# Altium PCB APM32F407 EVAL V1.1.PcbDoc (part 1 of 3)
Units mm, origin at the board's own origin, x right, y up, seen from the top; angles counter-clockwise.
Board outline 133.48 x 125.98 mm, 2 copper layers (Top Layer, Bottom Layer); 143 components, 208 nets, 809 pads, 486 vias.
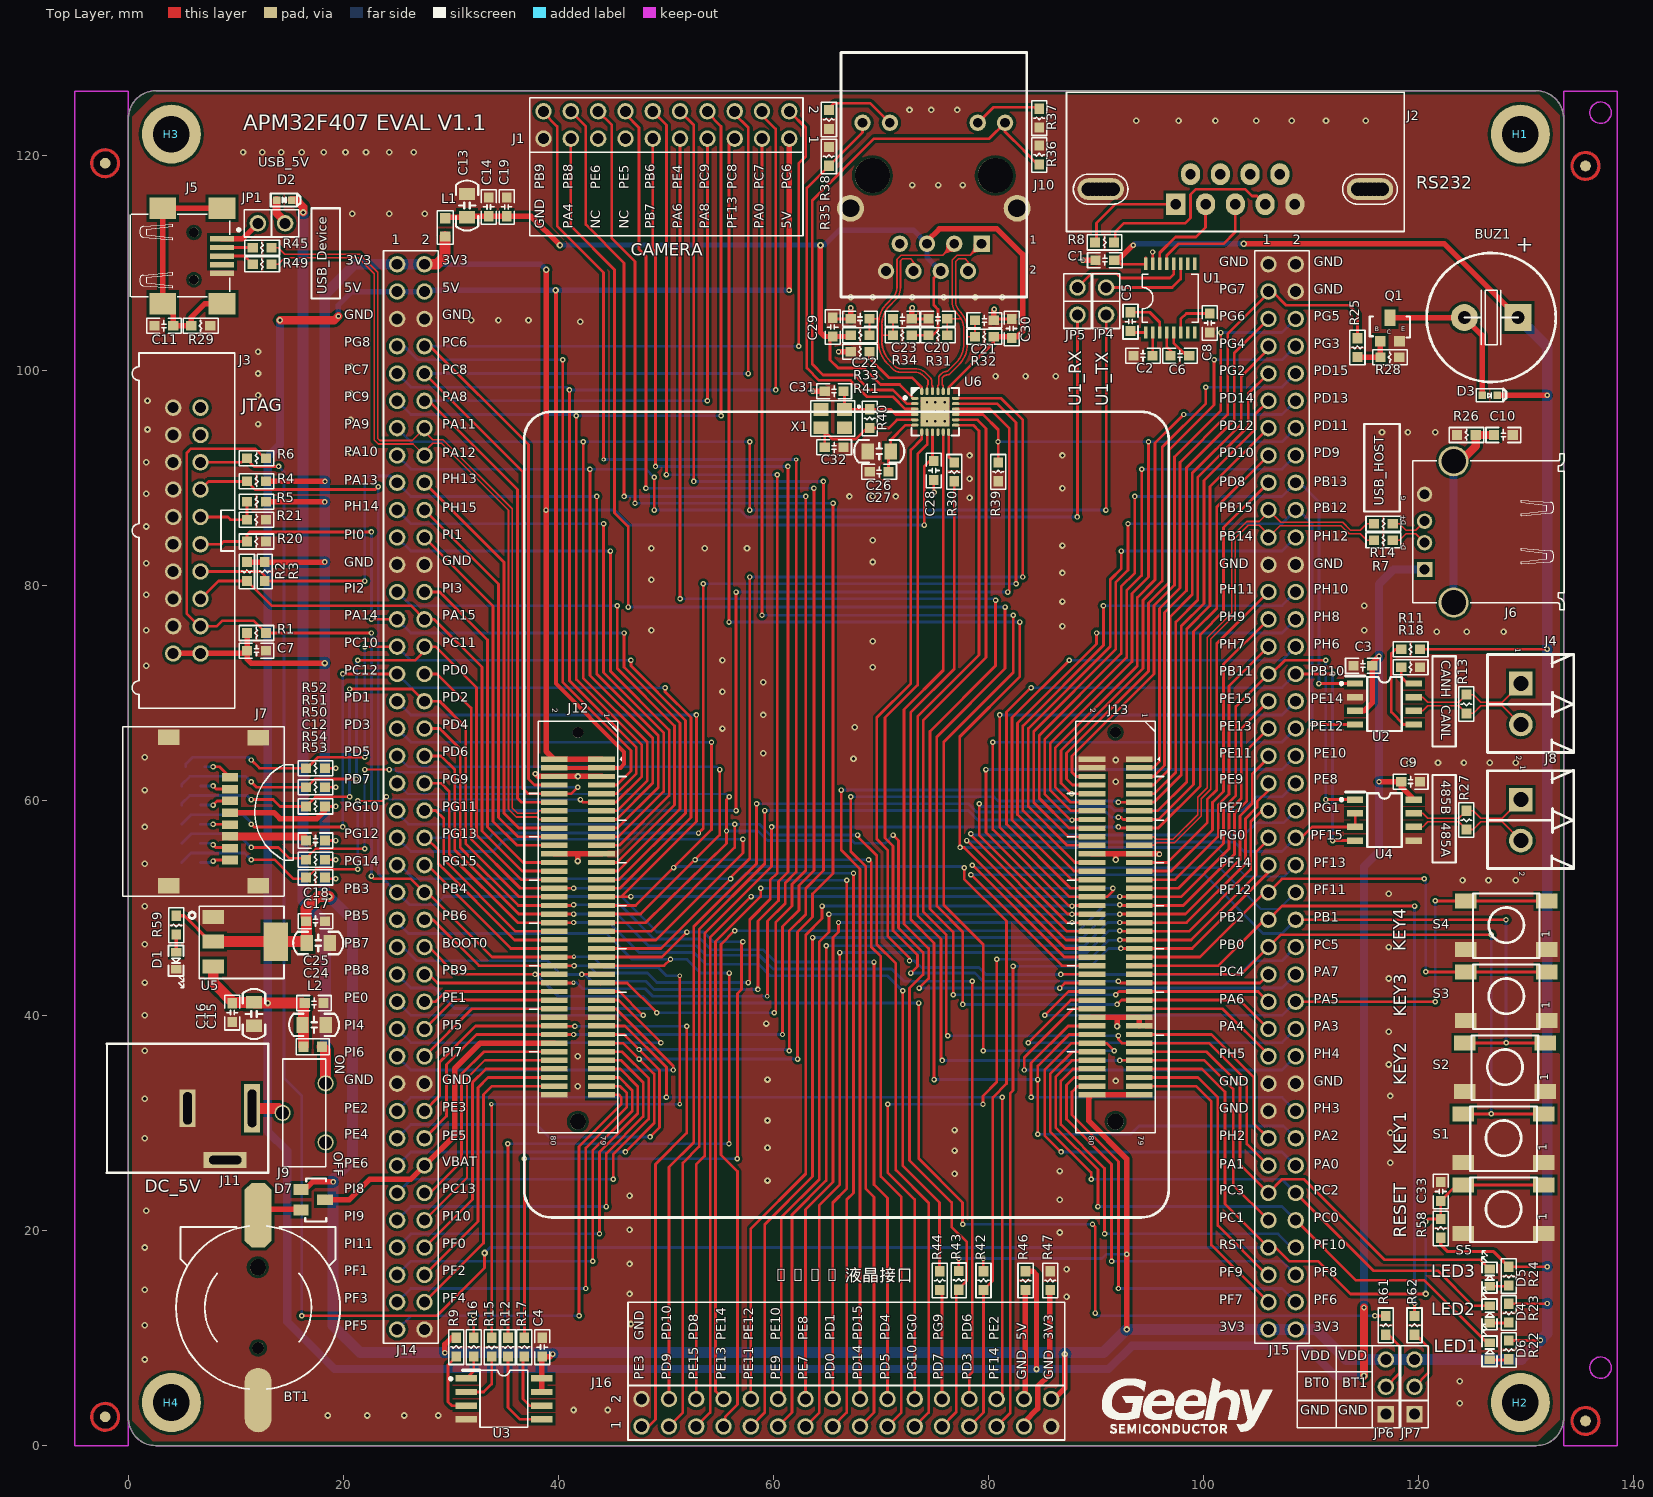
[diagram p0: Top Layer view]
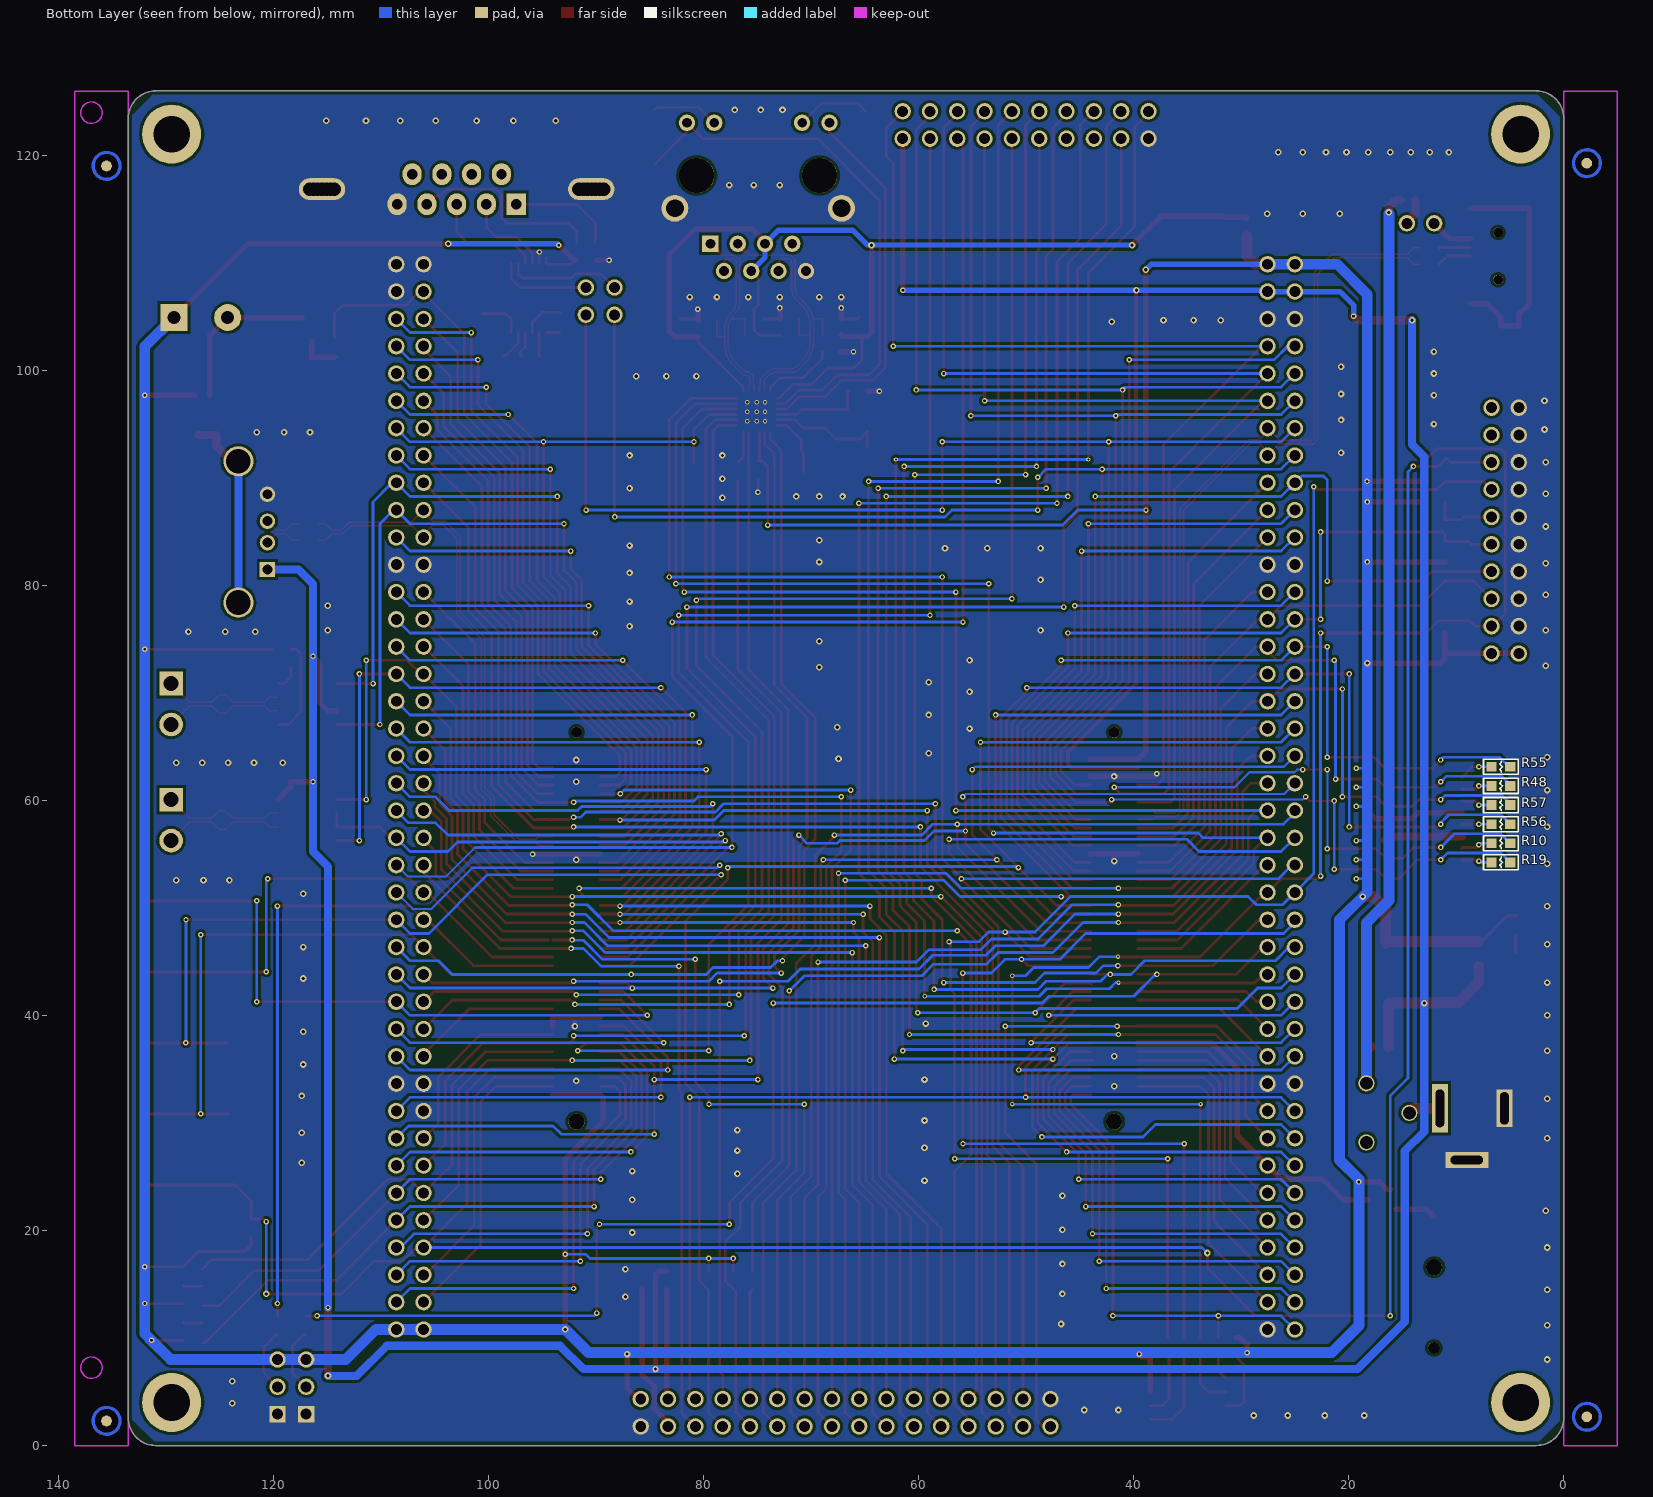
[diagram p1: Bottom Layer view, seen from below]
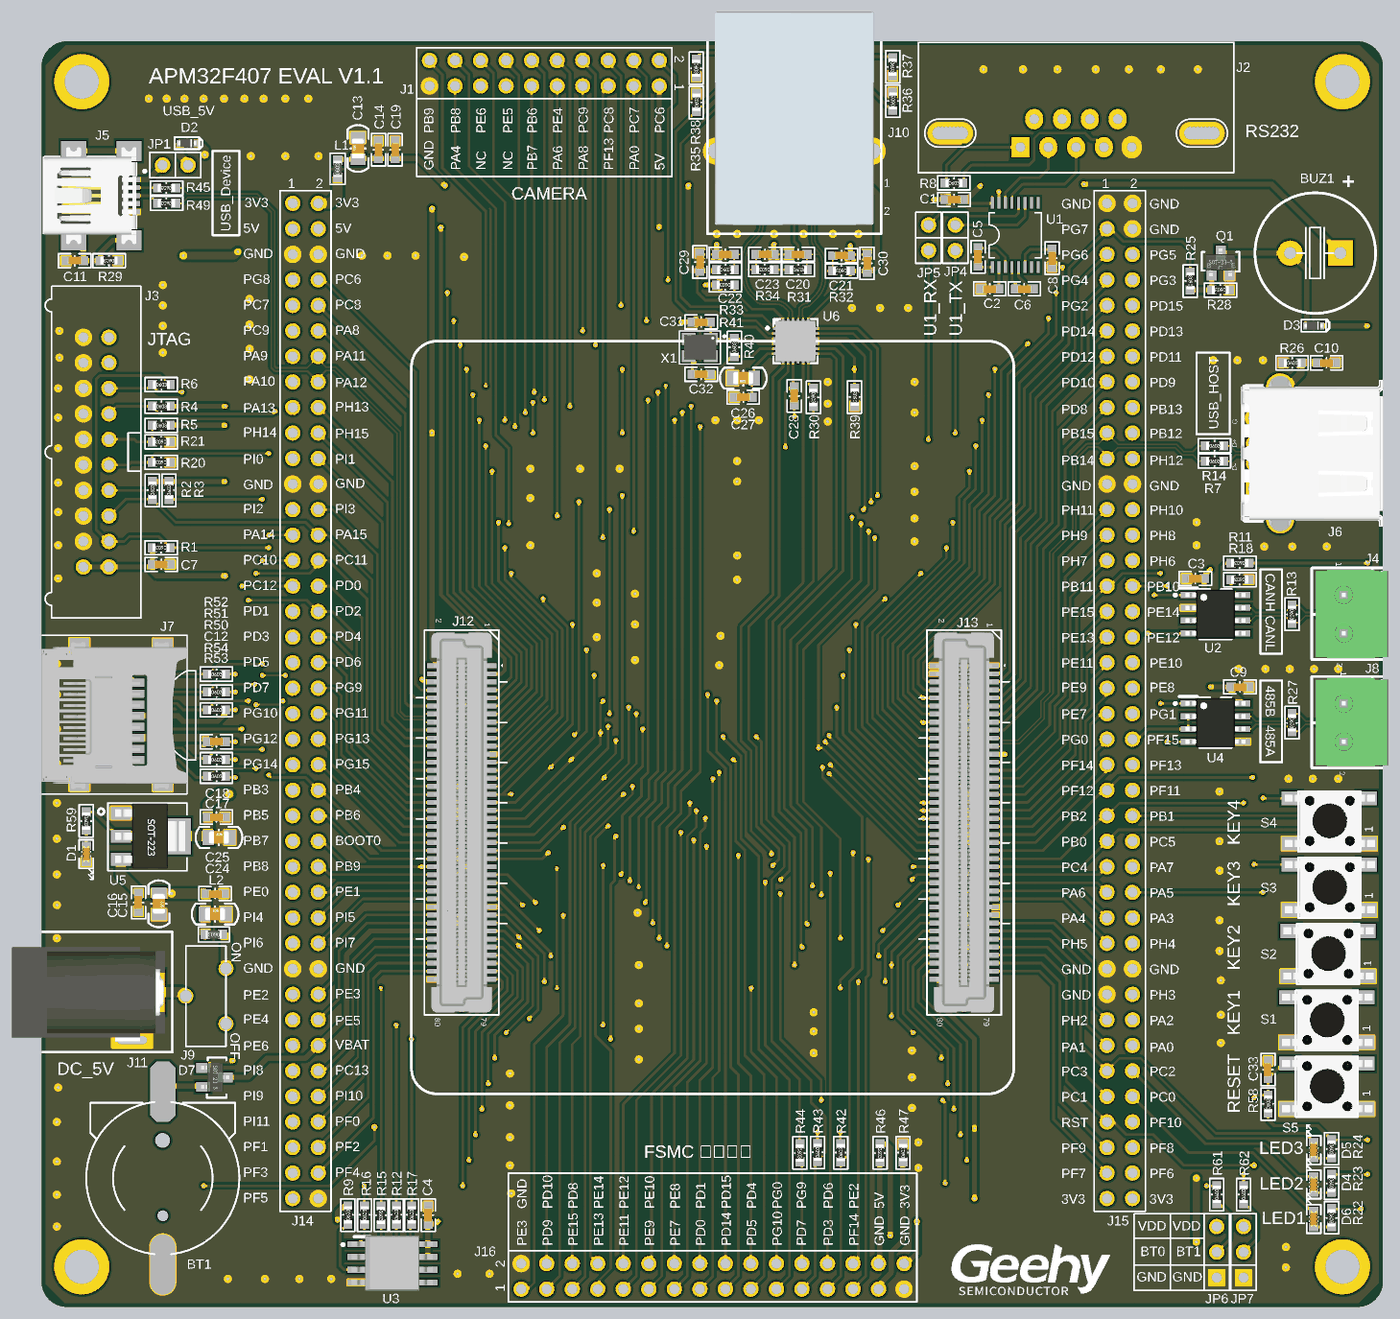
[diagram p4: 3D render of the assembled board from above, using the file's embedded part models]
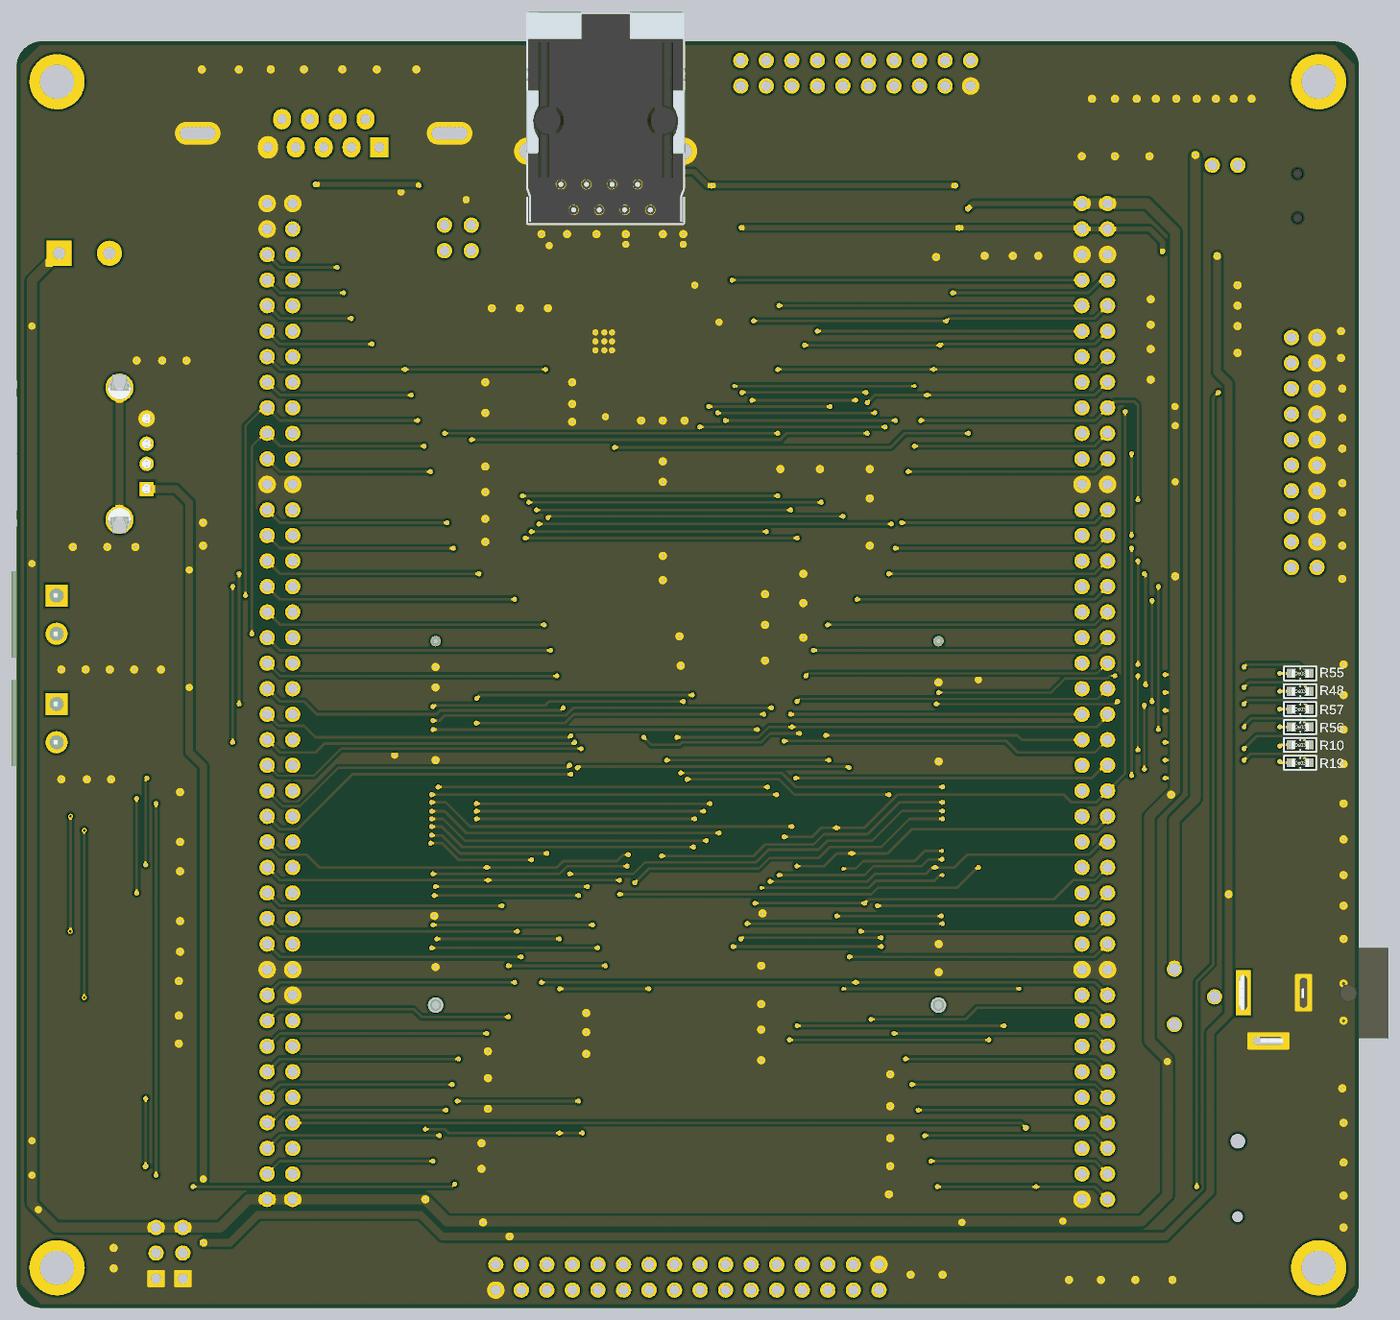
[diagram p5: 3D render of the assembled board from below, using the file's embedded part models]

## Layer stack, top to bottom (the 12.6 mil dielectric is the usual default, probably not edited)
Top Layer: signal copper 0.0356
Dielectric: dielectric 0.32, FR-4, Dk 4.8
Bottom Layer: signal copper 0.0356

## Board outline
0,2.54 ccw(c2.54,2.54) 2.54,0 130.937,0 ccw(c130.937,2.54) 133.477,2.54 133.477,123.444 ccw(c130.937,123.444) 130.937,125.984 2.54,125.984 ccw(c2.54,123.444) 0,123.444

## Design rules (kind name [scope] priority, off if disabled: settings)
Clearance Clearance_1 [IsRegion] p1: gap=0.254
Clearance [All] p2: gap=0.152
DiffPairsRouting [All] p1: maxlimit=0.178 minlimit=0.178 mostfreqgap=0.178 maxuncoupledlength=12.7
HoleSize [All] p1: absolutevalues=TRUE maxlimit=25.4 minlimit=0.025 maxpercent=80.000 minpercent=20.000
HoleToHoleClearance [All] p1: gap=0 allowstackedmicrovias=TRUE
MinimumSolderMaskSliver [All] p1: minsoldermaskwidth=0
PolygonConnect [All] p1: connectstyle=Direct reliefconductorwidth=0.254 reliefentries=4 polygonreliefangle="90 Angle" airgapwidth=0.254
RoutingVias [All] p1: holewidth=0.711 width=1.27 viastyle="Through Hole" minholewidth=0.025 minwidth=0.025 maxholewidth=0.711 maxwidth=1.27
SilkToSilkClearance [All] p1: silktosilkclearance=0
SilkToSolderMaskClearance [IsPad] p1: minsilkscreentomaskgap=0 clearancetoexposedcopper=TRUE
SolderMaskExpansion [All] p1: expansion=0.102
Width [All] p1: maxlimit=2.54 minlimit=0.025 preferedwidth=0.254 minimp=50.000000 maximp=50.000000 favimp=50.000000
22 further rules are at their usual default settings.

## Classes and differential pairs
component class 04_ETH: C13 C14 C19 C20 C21 C22 C23 C26 C27 C28 C29 C30 C31 C32 J10 L1 R30 R31 R32 R33 R34 R35 R36 R37 R38 R39 R40 R41 U6 X1
component class "01_Power Supply": C15 C16 C17 C18 C24 C25 D1 J9 J11 L2 R59 U5
component class 02_MCU_Connect: J12 J13
component class 03_GPIO: BT1 D7 H1 H2 H3 H4 J14 J15 JP6 JP7 R61 R62
component class 05_Memory&Camera&Button&BUZ: BUZ1 C4 C33 D3 J1 Q1 R9 R12 R15 R16 R17 R25 R28 R58 S1 S2 S3 S4 S5 U3
component class 06_TFCard&LED&LCD: C12 D4 D5 D6 J7 J16 R10 R19 R22 R23 R24 R42 R43 R44 R46 R47 R48 R50 R51 R52 R53 R54 R55 R56 R57
component class 07_Communication: C1 C2 C3 C5 C6 C8 C9 J2 J4 J8 JP4 JP5 R8 R11 R13 R18 R27 U1 U2 U4
component class 08_USB&JTAG: C7 C10 C11 D2 J3 J5 J6 JP1 R1 R2 R3 R4 R5 R6 R7 R14 R20 R21 R26 R29 R45 R49
differential pair NewDifferentialPair1: +NetJ8_2 -NetJ8_1
differential pair TPRX: +TPRX_P -TPRX_N
differential pair TPTX: +TPTX_P -TPTX_N
differential pair CAN: +CAN_P -CAN_N
differential pair OTG_FS: +PA12_OTG_FS_P -PA11_OTG_FS_N
differential pair OTG_HS: +PB15_OTG_HS_P -PB14_OTG_HS_N
differential pair NewDifferentialPair2: +NetJ6_3 -NetJ6_2

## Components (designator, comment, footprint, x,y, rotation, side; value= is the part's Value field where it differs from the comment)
BT1 "CR1220 holder" LI1220_1 12.065,12.827 r180 top
BUZ1 "SD1209T3-A1" BUZ5-12-0R5-9MM 126.746,104.902 r180 top
C1 "100nF" C0603 90.805,110.236 r0 top
C2 "100nF" C0603 94.361,101.346 r0 top
C3 "100nF" C0603 114.808,72.517 r0 top
C4 "100nF" C0603 38.481,9.144 r270 top
C5 "100nF" C0603 93.194,104.521 r270 top
C6 "100nF" C0603 97.79,101.346 r0 top
C7 "100nF" C0603 11.914,73.914 r0 top
C8 "100nF" C0603 100.56,104.394 r90 top
C9 "100nF" C0603 119.253,61.722 r0 top
C10 "100nF" C0603 127.865,93.98 r0 top
C11 "100nF" C0603 3.303,104.14 r180 top
C12 "100nF" C0603 17.399,56.261 r180 top
C13 "10uF" C0805 31.496,115.316 r90 top
C14 "100nF" C0603 33.528,115.189 r90 top
C15 "10uF" C0805 11.684,40.132 r270 top
C16 "100nF" C0603 9.652,40.259 r270 top
C17 "10uF" C0805 17.653,46.736 r0 top
C18 "100nF" C0603 17.399,48.768 r0 top
C19 "100nF" C0603 35.179,115.189 r90 top
C20 "10pF" C0603 75.287,104.775 r0 top
C21 "10pF" C0603 79.605,104.648 r180 top
C22 "10pF" C0603 68.048,104.775 r0 top
C23 "10pF" C0603 71.985,104.775 r180 top
C24 "10uF" C0805 17.272,39.116 r0 top
C25 "100nF" C0603 17.272,41.148 r0 top
C26 "10uF" C0805 69.826,92.456 r180 top
C27 "100nF" C0603 69.826,90.551 r180 top
C28 "100nF" C0603 74.906,90.678 r270 top
C29 "100nF" C0603 65.508,104.013 r90 top
C30 "100nF" C0603 82.145,103.886 r90 top
C31 "22pF" C0603 65.635,98.044 r0 top
C32 "22pF" C0603 65.635,92.837 r180 top
C33 "100nF" C0603 122.047,23.622 r270 top
D1 "19-217/GHC-YR1S2/3T" LED-0603 4.445,45.085 r270 top
D2 "SDM20U30-7" SOD-523 14.478,115.824 r0 top
D3 "1N4148WT-7" SOD-523 126.595,97.663 r0 top
D4 "19-217/GHC-YR1S2/3T" LED-0603 126.595,12.192 r90 top
D5 "19-217/GHC-YR1S2/3T" LED-0603 126.595,15.621 r90 top
D6 "19-217/GHC-YR1S2/3T" LED-0603 126.595,8.763 r90 top
D7 "BAT54CLT1G" SOT-23 17.272,22.86 r270 top
H1 "Value" THC5R5D3R4-M3-PTH#1 129.453,121.961 r0 top
H2 "Value" THC5R5D3R4-M3-PTH#2 129.286,2.921 r0 top
H3 "Value" THC5R5D3R4-M3-PTH#3 4.572,121.793 r0 top
H4 "Value" THC5R5D3R4-M3-PTH#4 4.191,3.683 r0 top
J1 "CAMERA_PORT" 2*10-2.54 61.468,124.079 r270 top
J2 "DB9" DB9/F 97.409,115.443 r0 top
J3 "JTAG" IDC20S 6.707,73.66 r180 top
J4 "UL0-TB13-15VC/3.81-02P" 2EDG2P-3R81-TH 129.5,68.961 r270 top
J5 "91-US01-302" USB-MiniB-SM-W 5.945,110.617 r270 top
J6 "U0010421122AB" USB-A-TH-W 121.896,84.963 r90 top
J7 "TF_CARD" SD-8 12.065,52.07 r90 top locked
J8 "UL0-TB13-15VC/3.81-02P" 2EDG2P-3R81-TH 129.5,58.166 r270 top
J9 "KEY" key-3 14.351,35.941 r270 top
J10 "HR911105A" RJ45-21R3X16R1X13R4-TH-W 74.906,113.665 r180 top
J11 "H-142-005B" DC-PORT-6R3-TH-W-234 8.509,28.956 r90 top
J12 "61083-084402LF" B2B2X40P-0R8-SM-Z-H7R7 41.805,48.224 r270 top locked
J13 "61083-084402LF" B2B2X40P-0R8-SM-Z-H7R7 91.805,48.224 r270 top locked
J14 "2*40-2.54" 2*40-2.54 24.995,109.855 r0 top locked
J15 "2*40-2.54" 2*40-2.54 106.021,109.855 r0 top locked
J16 "LCD_DIP_2X16_2.54" LCD-2*16-2.54 47.728,1.778 r90 top locked
JP1 "" SIP2 14.581,113.665 r180 top
JP4 "" SIP2 90.932,107.696 r270 top
JP5 "" SIP2 88.265,107.696 r270 top
JP6 "" SIP3 116.943,2.921 r90 top
JP7 "" SIP3 119.61,2.921 r90 top
L1 "470R/100MHz" L0603 29.464,113.284 r90 top
L2 "470R/100MHz" L0603 17.145,37.084 r180 top
Q1 "MMBT2222ALT1G" SOT-23-BCE 117.324,103.886 r0 top
R1 "10K" R0603 11.914,75.565 r180 top
R2 "10K" R0603 11.025,81.28 r90 top
R3 "10K" R0603 12.676,81.28 r90 top
R4 "10K" R0603 11.914,89.662 r0 top
R5 "10K" R0603 11.914,87.757 r0 top
R6 "10K" R0603 11.914,91.821 r0 top
R7 "0R" R0603 116.713,84.201 r0 top
R8 "0R" R0603 90.781,111.887 r0 top
R9 "0R" R0603 30.48,9.144 r90 top
R10 "0R" R0603 5.842,56.007 r180 bottom
R11 "NC" R0603 119.253,74.041 r180 top
R12 "22R" R0603 35.306,9.144 r90 top
R13 "120R" R0603 124.436,68.961 r270 top
R14 "0R" R0603 116.713,85.725 r0 top
R15 "22R" R0603 33.782,9.144 r270 top
R16 "22R" R0603 32.131,9.144 r90 top
R17 "22R" R0603 36.83,9.144 r90 top
R18 "10K" R0603 119.253,72.39 r180 top
R19 "0R" R0603 5.842,54.229 r180 bottom
R20 "10K" R0603 11.914,84.074 r180 top
R21 "10K" R0603 11.914,86.106 r180 top
R22 "510R" R0603 128.373,8.89 r270 top
R23 "510R" R0603 128.373,12.319 r270 top
R24 "510R" R0603 128.373,15.748 r270 top
R25 "1K" R0603 114.3,102.108 r90 top
R26 "1M" R0603 124.436,93.98 r0 top
R27 "120R" R0603 124.436,58.166 r270 top
R28 "10K" R0603 117.324,101.219 r180 top
R29 "1M" R0603 6.731,104.14 r180 top
R30 "510R" R0603 76.811,90.551 r270 top
R31 "49.9R" R0603 75.287,103.251 r0 top
R32 "49.9R" R0603 79.605,103.124 r180 top
R33 "49.9R" R0603 68.048,103.251 r0 top
R34 "49.9R" R0603 71.985,103.251 r180 top
R35 "10K" R0603 65.151,119.888 r90 top
R36 "10K" R0603 84.709,120.015 r90 top
R37 "510R" R0603 84.709,123.444 r270 top
R38 "510R" R0603 65.151,123.317 r270 top
R39 "10K" R0603 80.899,90.551 r90 top
R40 "1M" R0603 68.937,95.504 r90 top
R41 "12.1K" R0603 68.048,101.727 r180 top
R42 "4.7K" R0603 79.526,15.342 r90 top
R43 "4.7K" R0603 77.216,15.367 r90 top
R44 "NC" R0603 75.462,15.342 r270 top
R45 "0R" R0603 12.446,111.379 r180 top
R46 "0R" R0603 83.439,15.342 r270 top
R47 "NC" R0603 85.725,15.342 r90 top
R48 "0R" R0603 5.842,61.341 r180 bottom
R49 "0R" R0603 12.446,109.855 r180 top
R50 "10K" R0603 17.399,59.436 r0 top
R51 "10K" R0603 17.399,61.214 r0 top
R52 "10K" R0603 17.399,62.992 r0 top
R53 "10K" R0603 17.399,52.832 r0 top
R54 "10K" R0603 17.399,54.483 r0 top
R55 "0R" R0603 5.842,63.119 r180 bottom
R56 "0R" R0603 5.842,57.785 r180 bottom
R57 "0R" R0603 5.842,59.563 r180 bottom
R58 "10K" R0603 122.047,20.193 r90 top
R59 "2K" R0603 4.445,48.387 r270 top
R61 "10K" R0603 116.943,11.176 r90 top
R62 "10K" R0603 119.61,11.176 r90 top
S1 "TD-06XB(黑色）" SW-SMD-6x6x7-1 127.889,28.575 r180 top
S2 "TD-06XB(黑色）" SW-SMD-6x6x7-1 128.016,35.179 r180 top
S3 "TD-06XB(黑色）" SW-SMD-6x6x7-1 128.143,41.783 r180 top
S4 "TD-06XB(黑色）" SW-SMD-6x6x7-1 128.143,48.387 r180 top
S5 "TD-06XB(黑色）" SW-SMD-6x6x7-1 127.889,21.971 r180 top
U1 "ST3232ECTR" TSSOP16 94.615,103.505 r90 top
U2 "TJA1050" SOIC8-1R27-5X4 116.816,68.961 r0 top
U3 "W25Q16JVSNIQ" SOIC8-1R27-5R3X5R3 34.925,4.342 r0 top
U4 "MAX485" SOIC8-1R27-5X4 116.816,58.166 r0 top
U5 "TLV1117-33IDCYR" SOT223-4 10.795,46.863 r270 top
U6 "LAN8720A-CP-TR" QFN24-0R5-4X4-T 75.033,96.139 r0 top
X1 "25MHz" XTAL3225 65.508,95.504 r180 top

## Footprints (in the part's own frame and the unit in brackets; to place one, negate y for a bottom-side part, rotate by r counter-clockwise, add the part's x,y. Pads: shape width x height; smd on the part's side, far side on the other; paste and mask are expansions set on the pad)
2*10-2.54 [mil]
  round 60 hole 40: 1(100,0) 2(0,0) 3(100,-100) 4(0,-100) 5(100,-200) 6(0,-200) 7(100,-300) 8(0,-300) 9(100,-400) 10(0,-400) 11(100,-500) 12(0,-500) 13(100,-600) 14(0,-600) 15(100,-700) 16(0,-700) 17(100,-800) 18(0,-800) 19(100,-900) 20(0,-900)
  silkscreen extent -50,-950 150,50
2*40-2.54 [mil]
  round 60 hole 40: 1(0,0) 2(100,0) 3(0,-100) 4(100,-100) 5(0,-200) 6(100,-200) 7(0,-300) 8(100,-300) 9(0,-400) 10(100,-400) 11(0,-500) 12(100,-500) 13(0,-600) 14(100,-600) 15(0,-700) 16(100,-700) 17(0,-800) 18(100,-800) 19(0,-900) 20(100,-900) 21(0,-1000) 22(100,-1000) 23(0,-1100) 24(100,-1100) 25(0,-1200) 26(100,-1200) 27(0,-1300) 28(100,-1300) 29(0,-1400) 30(100,-1400) 31(0,-1500) 32(100,-1500) 33(0,-1600) 34(100,-1600) 35(0,-1700) 36(100,-1700) 37(0,-1800) 38(100,-1800) 39(0,-1900) 40(100,-1900) 41(0,-2000) 42(100,-2000) 43(0,-2100) 44(100,-2100) 45(0,-2200) 46(100,-2200) 47(0,-2300) 48(100,-2300) 49(0,-2400) 50(100,-2400) 51(0,-2500) 52(100,-2500) 53(0,-2600) 54(100,-2600) 55(0,-2700) 56(100,-2700) 57(0,-2800) 58(100,-2800) 59(0,-2900) 60(100,-2900) 61(0,-3000) 62(100,-3000) 63(0,-3100) 64(100,-3100) 65(0,-3200) 66(100,-3200) 67(0,-3300) 68(100,-3300) 69(0,-3400) 70(100,-3400) 71(0,-3500) 72(100,-3500) 73(0,-3600) 74(100,-3600) 75(0,-3700) 76(100,-3700) 77(0,-3800) 78(100,-3800) 79(0,-3900) 80(100,-3900)
  silkscreen extent -50,-3950 150,50
2EDG2P-3R81-TH [mm]
  rect 2.2x2.2 hole 1.4: 1(-1.905,0)
  round 2.2 hole 1.4: 2(1.905,0)
  silkscreen extent -4.61,-3.1 4.51,4.92, body extent -4.4,-2.72 4.4,4.48, height 9.1
B2B2X40P-0R8-SM-Z-H7R7 [mm]
  rect 0.5x2.5 smd: 1(-15.6,2.2) 2(-15.6,-2.2) 3(-14.8,2.2) 4(-14.8,-2.2) 5(-14,2.2) 6(-14,-2.2) 7(-13.2,2.2) 8(-13.2,-2.2) 9(-12.4,2.2) 10(-12.4,-2.2) 11(-11.6,2.2) 12(-11.6,-2.2) 13(-10.8,2.2) 14(-10.8,-2.2) 15(-10,2.2) 16(-10,-2.2) 17(-9.2,2.2) 18(-9.2,-2.2) 19(-8.4,2.2) 20(-8.4,-2.2) 21(-7.6,2.2) 22(-7.6,-2.2) 23(-6.8,2.2) 24(-6.8,-2.2) 25(-6,2.2) 26(-6,-2.2) 27(-5.2,2.2) 28(-5.2,-2.2) 29(-4.4,2.2) 30(-4.4,-2.2) 31(-3.6,2.2) 32(-3.6,-2.2) 33(-2.8,2.2) 34(-2.8,-2.2) 35(-2,2.2) 36(-2,-2.2) 37(-1.2,2.2) 38(-1.2,-2.2) 39(-0.4,2.2) 40(-0.4,-2.2) 41(0.4,2.2) 42(0.4,-2.2) 43(1.2,2.2) 44(1.2,-2.2) 45(2,2.2) 46(2,-2.2) 47(2.8,2.2) 48(2.8,-2.2) 49(3.6,2.2) 50(3.6,-2.2) 51(4.4,2.2) 52(4.4,-2.2) 53(5.2,2.2) 54(5.2,-2.2) 55(6,2.2) 56(6,-2.2) 57(6.8,2.2) 58(6.8,-2.2) 59(7.6,2.2) 60(7.6,-2.2) 61(8.4,2.2) 62(8.4,-2.2) 63(9.2,2.2) 64(9.2,-2.2) 65(10,2.2) 66(10,-2.2) 67(10.8,2.2) 68(10.8,-2.2) 69(11.6,2.2) 70(11.6,-2.2) 71(12.4,2.2) 72(12.4,-2.2) 73(13.2,2.2) 74(13.2,-2.2) 75(14,2.2) 76(14,-2.2) 77(14.8,2.2) 78(14.8,-2.2) 79(15.6,2.2) 80(15.6,-2.2)
  round 1 hole 1: 81(-18.1,0)
  round 1.5 hole 1.5: 82(18.1,0)
  silkscreen extent -19.15,-4.5 19.15,4.5, body extent -18.9,-3 18.9,3, height 7.75
BUZ5-12-0R5-9MM [mm]
  rect 2.5x2.5 hole 1.2: 1(-2.5,0)
  round 2.5 hole 1.2: 2(2.5,0)
  silkscreen extent -6,-6 6,6, body extent -5.99,-6 6,6, height 9
C0603 [mm]
  rect 0.95x0.9 smd: 1(-0.875,0) 2(0.875,0)
  silkscreen extent -1.61,-0.7 1.61,0.7, body extent -0.76,-0.41 0.76,0.36, height 0.78
C0805 [mm]
  rect 1.15x1.5 smd: 1(-1.079,0) 2(1.079,0)
  silkscreen extent -2.33,-1.04 2.33,1.04, body extent -1,-0.62 1,0.63, height 0.78
DB9/F [mil]
  round 50 hole 50: 0(-320,55) 0(-305,55) 0(-290,55) 0(-275,55) 0(-260,55) 0(-245,55) 0(-230,55) 0(666,55) 0(681,55) 0(696,55) 0(711,55) 0(726,55) 0(741,55) 0(756,55)
  oval 170x80 hole 50: 0(-275,55) 0(711,55)
  rect 70x80 hole 38: 1(0,0)
  oval 70x80 hole 38: 2(109,0) 3(218,0) 4(327,0) 5(436,0) 6(54,110) 7(163,110) 8(272,110) 9(381,110)
  silkscreen extent -400,-100 836,410
DC-PORT-6R3-TH-W-234 [mm]
  rect 1.5x4 hole 0.8 slot 3 at 90 deg: 2(-2.4,-0.5)
  rect 3.5x1.5 hole 0.8 slot 3 at 0 deg: 3(2.4,3)
  rect 4.5x1.5 hole 0.8 slot 3.5 at 0 deg: 4(2.4,-3)
  silkscreen extent -3.6,-4.5 8.4,10.5, body extent -2.54,-3.76 6.86,11.44, height 11
IDC20S [mil]
  round 60 hole 40: 1(0,0) 2(100,0) 3(0,-100) 4(100,-100) 5(0,-200) 6(100,-200) 7(0,-300) 8(100,-300) 9(0,-400) 10(100,-400) 11(0,-500) 12(100,-500) 13(0,-600) 14(100,-600) 15(0,-700) 16(100,-700) 17(0,-800) 18(100,-800) 19(0,-900) 20(100,-900)
  silkscreen extent -125,-1100 250,200
key-3 [mm]
  round 1.5 hole 1.2: 1(5,0) 2(2.25,4) 3(7.75,4)
  silkscreen extent 0,0 10,4
L0603 [mm]
  rect 0.95x0.95 smd: 1(-0.85,0) 2(0.85,0)
  silkscreen extent -1.55,-0.75 1.55,0.75, body extent -0.8,-0.4 0.8,0.4, height 0.45
LCD-2*16-2.54 [mil]
  round 60 hole 40: 1(100,0) 2(0,0) 3(100,-100) 4(0,-100) 5(100,-200) 6(0,-200) 7(100,-300) 8(0,-300) 9(100,-400) 10(0,-400) 11(100,-500) 12(0,-500) 13(100,-600) 14(0,-600) 15(100,-700) 16(0,-700) 17(100,-800) 18(0,-800) 19(100,-900) 20(0,-900) 21(100,-1000) 22(0,-1000) 23(100,-1100) 24(0,-1100) 25(100,-1200) 26(0,-1200) 27(100,-1300) 28(0,-1300) 29(100,-1400) 30(0,-1400) 31(100,-1500) 32(0,-1500)
  silkscreen extent -50,-1550 150,50
LED-0603 [mm]
  rect 0.8x0.965 smd: 1(-0.8,0) 2(0.8,0)
  silkscreen extent -1.42,-0.7 2.51,0.72, body extent -0.81,-0.4 0.81,0.4, height 0.6
LI1220_1 [mm]
  round 1.1 hole 1.1 unplated: 0(0,3.75)
  round 1.5 hole 1.5 unplated: 0(0.025,-3.75)
  oct 2.5x6 smd: 1(0,-8.6)
  oval 2.5x6 smd: 2(0,8.6)
  silkscreen extent -7.62,-7.57 7.62,7.57
QFN24-0R5-4X4-T [mm]
  oval 0.7x0.28 smd: 1(-1.9,1.25) 2(-1.9,0.75) 3(-1.9,0.25) 4(-1.9,-0.25) 5(-1.9,-0.75) 6(-1.9,-1.25) 13(1.9,-1.25) 14(1.9,-0.75) 15(1.9,-0.25) 16(1.9,0.25) 17(1.9,0.75) 18(1.9,1.25)
  oval 0.28x0.7 smd: 7(-1.25,-1.9) 8(-0.75,-1.9) 9(-0.25,-1.9) 10(0.25,-1.9) 11(0.75,-1.9) 12(1.25,-1.9) 19(1.25,1.9) 20(0.75,1.9) 21(0.25,1.9) 22(-0.25,1.9) 23(-0.75,1.9) 24(-1.25,1.9)
  rect 2.7x2.7 smd: 25(0,0)
  silkscreen extent -2.92,-2.2 2.2,2.2, body extent -2,-2 2,2, height 0.75
R0603 [mm]
  rect 0.95x0.9 smd: 1(-0.875,0) 2(0.875,0)
  silkscreen extent -1.61,-0.7 1.61,0.7, body extent -0.82,-0.43 0.88,0.37, height 0.56
RJ45-21R3X16R1X13R4-TH-W [mil]
  rect 60x60 hole 36: 1(-175,75)
  round 60 hole 36: 2(-125.2,175) 3(-75,75) 4(-25.2,175) 5(25,75) 6(74.8,175) 7(125,75) 8(174.8,175)
  round 60 hole 35.43: 9(-260.83,-367.91) 10(-160.83,-367.91) 11(160.83,-367.91) 12(260.83,-367.91)
  round 98.43 hole 64.96: 13(-304.92,-54.92) 14(304.92,-54.92)
  round 128 hole 128: 15(-225,-175) 16(225,-175)
  silkscreen extent -340,-625 340,270, body extent -311,-600 311,235, height 488
SD-8 [mm]
  rect 0.8x1.5 smd: 1(10.08,2.6) 2(8.98,2.6) 3(7.88,2.6) 4(6.78,2.6) 5(5.68,2.6) 6(4.58,2.6) 7(3.48,2.6) 8(2.38,2.6)
  rect 1.45x2 smd: G1(13.75,0) G2(13.8,8.3) G3(0,8.3) G4(0,0)
  silkscreen extent -1.01,-3.28 14.79,12.58, body extent -0.5,-2.44 14.1,12.06, height 2.26
SIP2 [mil]
  round 60 hole 40: 1(0,0) 2(100,0)
  silkscreen extent -50,-50 150,50
SIP3 [mil]
  rect 60x60 hole 40: 1(0,0)
  round 60 hole 40: 2(100,0) 3(200,0)
  silkscreen extent -50,-50 250,50
SOD-523 [mm]
  rect 0.7x0.7 smd: 1(-0.7,0) 2(0.7,0)
  silkscreen extent -1.24,-0.58 1.53,0.61, body extent -0.92,-0.4 0.91,0.45, height 0.71
SOIC8-1R27-5R3X5R3 [mm]
  rect 2x0.6 smd: 1(-3.5,1.905) 2(-3.5,0.635) 3(-3.5,-0.635) 4(-3.5,-1.905) 5(3.5,-1.905) 6(3.5,-0.635) 7(3.5,0.635) 8(3.5,1.905)
  silkscreen extent -5.06,-2.65 2.22,2.65, body extent -4.08,-2.71 4.02,2.75, height 1.75
SOIC8-1R27-5X4 [mm] "SOIC, 8-Leads, Body 4.90x3.85mm, Pitch 1.27mm, IPC Medium Density"
  rect 1.5x0.6 smd: 1(-2.725,1.905) 2(-2.725,0.635) 3(-2.725,-0.635) 4(-2.725,-1.905) 5(2.725,-1.905) 6(2.725,-0.635) 7(2.725,0.635) 8(2.725,1.905)
  silkscreen extent -4.12,-2.5 1.6,2.6, body extent -3,-2.45 3,2.45, height 1.75
SOT223-4 [mm]
  rect 1.3x2 smd: 1(-2.3,-2.9) 2(0,-2.9) 3(2.3,-2.9)
  rect 3.6x2.3 smd: 4(0,2.9)
  silkscreen extent -3.3,-5.17 3.43,3.68, body extent -3.25,-3.48 3.25,3.48, height 1.7
SOT-23 [mm]
  rect 1x1.4 smd: 1(-0.95,-1.2) 2(0.95,-1.2)
  rect 1x1.5 smd: 3(0,1)
  silkscreen extent -1.98,-0.82 2.02,1.12, body extent -1.45,-1.4 1.45,1.4, height 1.2
SOT-23-BCE [mm]
  rect 1x1 smd: B(-0.9,-1.2) E(0.9,-1.2)
  rect 1x1.5 smd: C(0,1)
  silkscreen extent -1.88,-0.82 1.88,1.12, body extent -1.45,-1.3 1.45,1.5, height 1.2
SW-SMD-6x6x7-1 [mm]
  rect 2x1.4 smd: 1(-3.75,2.25) 2(3.75,2.25) 3(-3.75,-2.25) 4(3.75,-2.25)
  silkscreen extent -3.1,-2.95 3.1,3.05, body extent -4.55,-3 4.45,3, height 4.3
THC5R5D3R4-M3-PTH#1 [mm]
  round 5.5 hole 3.4: 1(0,0)
THC5R5D3R4-M3-PTH#2 [mm]
  round 5.5 hole 3.4: 1(0.167,1.079)
THC5R5D3R4-M3-PTH#3 [mm]
  round 5.5 hole 3.4: 1(-0.572,0.168)
THC5R5D3R4-M3-PTH#4 [mm]
  round 5.5 hole 3.4: 1(-0.191,0.317)
TSSOP16 [mm]
  rect 1.15x0.3 smd: 1(0,0) 2(0,-0.65) 3(0,-1.3) 4(0,-1.95) 5(0,-2.6) 6(0,-3.25) 7(0,-3.9) 8(0,-4.55) 9(6.4,-4.55) 10(6.4,-3.9) 11(6.4,-3.25) 12(6.4,-2.6) 13(6.4,-1.95) 14(6.4,-1.3) 15(6.4,-0.65) 16(6.4,0)
  silkscreen extent 0.94,-4.88 5.42,0.33
USB-A-TH-W [mm]
  rect 1.428x1.428 hole 0.92: 1(-3.5,1.35)
  round 1.428 hole 0.92: 2(-1,1.35) 3(1,1.35) 4(3.5,1.35)
  round 2.8 hole 2.3: 5(-6.57,-1.35) 6(6.57,-1.35)
  silkscreen extent -7.25,-11.63 7.25,2.47, body extent -7.9,-11.63 7.9,2.47, height 7.71
USB-MiniB-SM-W [mm]
  rect 0.5x2.25 smd: 1(-1.6,2.75) 2(-0.8,2.75) 3(0,2.75) 4(0.8,2.75) 5(1.6,2.75)
  rect 2x2.5 smd: 6(-4.45,2.75) 7(-4.45,-2.75) 8(4.45,2.75) 9(4.45,-2.75)
  round 0.9 hole 0.9 unplated: ""(-2.2,0.15) ""(2.2,0.15)
  silkscreen extent -3.9,-5.75 3.8,4.44, body extent -4.8,-5.75 4.8,3.5, height 3.97
XTAL3225 [mm]
  rect 1.4x1.2 smd: 1(-1.1,-0.85) 2(1.1,-0.85) 3(1.1,0.85) 4(-1.1,0.85)
  silkscreen extent -2.48,-1.65 2.04,1.65, body extent -1.63,-1.28 1.57,1.22, height 0.91

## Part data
BT1: library part BATTERY, "Battery"
BUZ1: library part 102BA-00003OD.01, "DIP,封装/外壳12x9mm,额定电压DC3V,频率2048Hz,黑色,间距5mm"
C1 C2 C3 C4 C5 C6 C7 C8 C9 C10 C11 C12 C14 C16 C18 C19 C25 C27 C28 C29 C30 C33: "安装方式SMD,电容量100nF,额定电压50V,偏差±10%,材质X7R,0603"
C13 C15 C17 C24 C26: library part CAP-2-NP-P_1, "SMD,电容量10uF,额定电压50V,偏差±10%,材质X5R,0805"
C20 C21 C22 C23: library part 101CC-00365BE.01, "SMD,电容量10pF,额定电压50V,偏差±1pF,材质C0G,0603"
C31 C32: library part 101CC-00036IA.01, "安装方式SMD,电容量22pF,额定电压50V,偏差±5%,材质NP0,0603"
D1 D4 D5 D6: "SMD,封装/间距0603,额定电压3.3V,亮度普亮,绿色"
D2: library part 101DS-00037AF.01, "SMD,封装外壳SOD-523（0603）,额定电压30V,电流200mA"
D3: "SMD,SOD-523（0603）,额定电压80V,电流125mA"
D7: library part 101DS-00053BA.01, "安装方式SMD,SOT-23,额定电压30V,电流200mA"
H1 H2 H3 H4: library part M3-PTH
J3: library part "Header 10X2", "Header, 10-Pin, Dual row"
J4 J8: "安装方式DIP,座子,封装脚距3.81mm,180度,2PIN,塑高/针长9.2/3.5mm,绿色,不带螺柱"
J5: "安装方式SMD,MiniB口,封装尺寸9.3x7.7x3.95mm,触点材质：磷铜,颜色：黑色,90度,5PIN+4PIN(定位脚)+2PIN(定位脚),卧式"
J6: "DIP,A口,封装尺寸14.3x14.2x7.1mm,触点材质/颜色铜镀镍/白色,90度,4+2PIN,卧式"
J10: library part J0011D21B
J11: "安装方式DIP,插座,封装尺寸2.0x6.3mm,触点材质/颜色镀锡/黑色,90度,3PIN"
J12 J13: library part 101NH-00011CO.01, "SMD,插头,封装脚距0.80mm,180度,引脚数目2x40PIN,塑高/针长7.7mm/无,白色"
J14 J15: library part 101NH-00011CO.01
JP1 JP4 JP5: library part JP2
JP6 JP7: library part Jumper3
L1 L2: "SMD,电感值无,额定电流1A,屏蔽式,0603,阻值/频率470R/100MHz"
Q1: "SMD,封装形式SOT-23,耐压值40V,额定电流600mA,耗散功率225mW"
R7 R8 R9 R10 R11 R14 R19 R44 R45 R46 R47 R48 R49 R55 R56 R57: "SMD,阻值0R,精度±1%,0603,额定功率1/10W"
R22 R23 R24 R30 R37 R38: library part 101RC-02070BW.01, "安装方式SMD,阻值510R,精度±0.1%,0603,额定功率1/10W，温度系数±50PPM/℃"
R40: library part 101RC-01958BW.01, "安装方式SMD,阻值1M,精度±0.1%,0603,额定功率1/10W，温度系数±25PPM/℃"
R41: library part 101RC-01821BW.01, "安装方式SMD,阻值12.1K,精度±1%,0603,额定功率1/10W"
S1 S2 S3 S4 S5: "安装方式SMD,6.0x6.0x7.0mm,4PIN,180度,黑色"
U1: library part ST3232, "3.3V/5V Dual RS232 Transceiver w/ Int. Cap."
U2: library part 101IK-00037AY.01, "安装方式SMD,SO-8,8PIN,高速CAN收发器(工作电压为4.75~5.25V)"
U3: library part 101IC-00010EA.01, "SMD,SOIC-8,8PIN,功能描述16M-bit flash（电压2.7V~3.6V）"
U4: library part 101IK-00033AR.01, "安装方式SMD,SOIC-8,8PIN,RS-485/RS-422收发器（工作电压4.75V~5.25V）"
U5: "安装方式SMD,SOT-223-4,4PIN,线性稳压器(输入电压 4.75V~10V,输出电压3.3V,输出电流800mA)"
U6: library part 101IK-00033AS.01, "安装方式SMD,QFN-24,24PIN,功能描述以太网PHY层芯片可通过RMII与带MAC功能的MCU通信(工作电压:1.6V~3.6V)"
X1: library part 101XB-00048BP.01, "安装方式SMD,材质金属外壳,3225,精度±30ppm,震荡频率25MHz，负载电容18pF"

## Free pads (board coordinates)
  round 1 smd: 1(-2.159,2.667) 1(-2.159,119.253) 1(135.509,2.286) 1(135.509,118.999)
  round 1 smd far side: 6(-2.159,2.667) 6(-2.159,119.253) 6(135.509,2.286) 6(135.509,118.999)

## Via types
v1: diameter 0.508, hole 0.254, Top Layer to Bottom Layer, 294 vias
v2: diameter 0.61, hole 0.305, Top Layer to Bottom Layer, 172 vias
v3: diameter 0.406, hole 0.203, Top Layer to Bottom Layer, 17 vias
v4: diameter 0.6, hole 0.3, Top Layer to Bottom Layer, 3 vias

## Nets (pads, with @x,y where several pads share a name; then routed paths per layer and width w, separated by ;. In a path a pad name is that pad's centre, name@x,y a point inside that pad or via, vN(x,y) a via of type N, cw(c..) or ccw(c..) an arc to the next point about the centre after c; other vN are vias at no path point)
+3V3: BUZ1.1 C1.2 C4.2 C7.1 C12.1 C17.1 C18.1 C28.1 D3.2 D7.1 J3.1 J3.2 J7.4 J12.1 J12.2 J13.79 J13.80 J14.1 J14.2 J15.79 J15.80 J16.31 JP6.3 JP7.3 L1.1 R1.2 R2.2 R3.2 R4.2 R5.2 R9.2 R11.1 R22.1 R23.1 R24.1 R42.2 R43.2 R50.2 R51.2 R52.2 R53.2 R54.2 R58.1 R59.1 U1.16 U3.7 U3.8 U5.2 U5.4 U6.9 | length 646.6
  Top Layer w0.254: R53.2@18.274,52.705 v1(19.28,52.705) ; R54.2@18.274,54.483 v1(19.28,54.483) ; C12.1@18.274,56.261 v1(19.28,56.261) ; R50.2@18.274,59.436 v1(19.28,59.436) ; R51.2@18.274,61.214 v1(19.28,61.214) ; R52.2@18.274,62.992 v1(19.28,62.992) ; v1(74.017,85.598) 74.017,91.059 74.511,91.553 C28.1@74.906,91.553 74.783,91.676 U6.9@74.783,94.239 ; R43.2@77.216,16.242 v1(77.216,17.399) ; v1(79.502,17.399) 79.502,16.241 R42.2@79.526,16.217 ; C1.2@91.68,110.236 91.924,110.236 92.305,109.855 94.565,109.855 U1.16@94.615,109.905 U1.16@94.615,110.466 ; R11.1@120.128,74.041 v1(131.953,74.041) ; R22.1@128.373,9.765 130.913,9.765 131.304,9.765 v1(131.318,9.779) ; R23.1@128.373,13.194 131.939,13.194 v1(131.953,13.208) ; R24.1@128.373,16.623 131.939,16.623 v1(131.953,16.637)
  Top Layer w0.3: R59.1@4.445,49.262 5.221,49.262 7.62,46.863 U5.2@7.895,46.863 ; R58.1@122.047,19.318 122.047,18.669 122.682,18.034 126.962,18.034 R24.1@128.373,16.623
  Top Layer w0.508: J3.2@4.167,73.66 J3.1@6.707,73.66 10.785,73.66 C7.1@11.039,73.914 ; J7.4@9.465,58.85 13.54,58.85 14.097,58.293 17.526,58.293 18.274,59.041 R50.2@18.274,59.436 ; R2.2@11.025,82.155 R3.2@12.676,82.155 18.25,82.155 v1(18.264,82.169) ; R1.2@11.039,75.565 C7.1@11.039,73.914 ; R5.2@12.789,87.757 v1(18.264,87.757) ; R4.2@12.789,89.662 v1(18.288,89.662) ; D7.1@16.072,23.81 16.444,23.81 17.145,24.511 v1(19.05,24.511) ; v2(18.264,72.771) 11.406,72.771 11.039,73.138 C7.1@11.039,73.914 ; v1(29.44,8.636) 29.44,9.398 30.061,10.019 R9.2@30.48,10.019 ; U3.7@38.425,4.977 U3.8@38.425,6.247 38.425,8.213 C4.2@38.481,8.269 39.233,8.269 v1(39.473,8.509) ; v2(38.862,109.347) 38.862,64.567 J12.2@39.605,63.824 J12.1@44.005,63.824 ; J16.31@85.828,4.318 86.082,4.318 87.098,5.334 v2(87.098,8.509) ; C1.2@91.924,110.236 92.051,110.236 v1(93.448,111.633) ; v2(92.837,10.795) v1(92.837,17.78) 92.837,26.67 89.316,30.191 89.316,32.335 J13.80@89.605,32.624 J13.79@94.005,32.624 ; v2(103.735,111.76) 122.388,111.76 BUZ1.1@129.246,104.902 ; D3.2@127.295,97.663 v1(131.953,97.663)
  Top Layer w1.016: U5.2@7.895,46.863 U5.4@13.695,46.863 16.447,46.863 C17.1@16.573,46.736 16.573,49.1 16.524,49.149 16.524,49.925 17.653,51.054 v2(18.669,51.054) ; J14.2@27.535,109.855 28.702,109.855 29.464,110.617 L1.1@29.464,112.434
  Bottom Layer w0.254: 18.264,54.483 v1(19.28,54.483) ; 18.264,56.261 v1(19.28,56.261) ; 18.264,59.436 v1(19.28,59.436) ; 18.264,61.214 v1(19.28,61.214) ; 18.264,62.992 v1(19.28,62.992) ; 18.391,52.705 v1(19.28,52.705) ; v1(38.838,86.995) 45.188,86.995 46.585,85.598 v1(74.017,85.598) ; v1(77.216,17.399) v1(79.502,17.399) 90.551,17.399 90.932,17.78 v1(92.837,17.78)
  Bottom Layer w0.508: J14.2@27.789,109.855 38.354,109.855 v2(38.862,109.347) ; v1(93.448,111.633) 93.575,111.76 v2(103.735,111.76)
  Bottom Layer w1.016: v1@19.026,24.511 19.026,11.176 21.566,8.636 v1(29.44,8.636) 90.678,8.636 v2(92.837,10.795) J15.79@106.021,10.795 J15.80@108.561,10.795 110.466,10.795 113.26,8.001 JP6.3@116.943,8.001 JP7.3@119.61,8.001 129.54,8.001 v1(131.318,9.779) 131.953,10.414 v1(131.953,13.208) v1(131.953,16.637) v1(131.953,74.041) v1(131.953,97.663) 131.953,102.195 BUZ1.1@129.246,104.902 ; 19.026,24.765 20.828,26.567 20.828,48.895 18.264,51.459 18.264,54.483 18.264,56.261 18.264,59.436 18.264,61.214 18.264,62.992 v2(18.264,72.771) v1(18.264,82.169) v1(18.264,87.757) 18.264,107.061 21.058,109.855 J14.1@24.995,109.855 J14.2@27.535,109.855 J14.2@27.789,109.855
+3V3_ETH: C13.1 C14.1 C19.1 C29.1 C30.1 J10.4 J10.5 L1.2 R31.1 R32.1 R33.1 R34.1 U6.1 U6.19 | length 108.9
  Top Layer w0.254: C29.1@65.508,103.138 65.254,102.884 65.254,100.965 66.016,100.203 68.429,100.203 69.953,98.679 71.731,98.679 73.021,97.389 U6.1@73.133,97.389 ; R34.1@72.86,103.251 R31.1@74.412,103.251 74.779,103.251 75.287,103.759 75.287,105.664 74.906,106.045 74.906,108.58 J10.4@75.546,109.22 ; U6.19@76.283,98.039 76.283,98.405 80.48,102.602 R32.1@80.48,103.124
  Top Layer w0.508: L1.2@29.464,114.134 29.566,114.236 C13.1@31.496,114.236 31.574,114.314 C14.1@33.528,114.314 C19.1@35.179,114.314 37.451,114.314 v2(40.132,111.633) ; v2(64.365,111.633) 64.365,103.533 64.76,103.138 C29.1@65.508,103.138 67.06,103.138 R33.1@67.173,103.251 ; J10.5@74.271,111.76 74.271,112.014 75.414,113.157 80.772,113.157 83.161,110.768 83.161,103.622 82.663,103.124 R32.1@80.48,103.124
  Bottom Layer w0.508: v2@40.132,111.647 64.76,111.647 66.143,113.03 73.001,113.03 J10.5@74.271,111.76 74.271,110.495 J10.4@75.546,109.22
+5V: C3.2 C9.1 C15.1 C16.1 C24.1 C25.1 J1.1 J6.1 J12.3 J12.4 J14.3 J14.4 L2.2 R46.1 U2.3 U4.8 U5.3 | length 429.1
  Top Layer w0.381: J12.4@39.605,63.024 J12.3@44.005,63.024 45.752,63.024 46.101,63.373 46.101,64.516 39.751,70.866 v2@39.751,107.315
  Top Layer w0.508: v1(61.444,107.442) 61.468,107.466 J1.1@61.468,121.539 ; R46.1@83.439,16.217 84.113,16.217 84.455,15.875 v4(84.455,7.112) ; U2.3@114.091,68.326 114.911,68.326 115.683,69.098 C3.2@115.683,72.517 115.683,72.781 v1(116.308,73.406) ; v1(116.308,61.722) C9.1@118.378,61.722 118.378,61.234 U4.8@119.541,60.071
  Top Layer w0.762: v2(14.097,104.648) 19.153,104.648 v1(19.534,105.029) ; v2(114.911,6.477) v1(114.911,12.827)
  Top Layer w1.016: U5.3@7.895,44.563 7.895,43.046 9.73,41.212 C15.1@11.684,41.212 11.747,41.148 16.193,41.148 16.295,41.046 L2.2@16.295,37.084
  Bottom Layer w0.508: v1(19.534,105.029) 19.534,106.045 20.804,107.315 J14.3@24.995,107.315 J14.4@27.535,107.315 27.662,107.442 v2(39.727,107.442) v1(61.444,107.442)
  Bottom Layer w0.762: v2(14.097,104.648) 14.097,93.091 12.954,91.948 12.954,29.21 14.783,27.381 14.783,11.506 19.177,7.112 v4(84.455,7.112) 91.162,7.112 93.321,9.271 109.45,9.271 112.244,6.477 v2(114.911,6.477) ; v1(114.911,12.827) 114.911,53.848 116.308,55.245 v1(116.308,61.722) v1(116.308,73.406) 116.308,80.113 117.658,81.463 J6.1@120.546,81.463
  other v2: 12.954,41.148
+5V_IN: D2.2 J9.2 L2.1 | length 87.1
  Top Layer w0.762: D2.2@15.178,115.824 15.621,115.824 16.256,115.189 v4(16.256,114.681)
  Top Layer w1.016: L2.1@17.995,37.084 18.351,36.728 J9.2@18.351,33.691
  Bottom Layer w1.016: v4@16.256,114.554 16.256,50.673 18.351,48.578 J9.2@18.351,33.691
BOOT0: J12.52 J14.52 R61.2 | length 119.7
  Top Layer w0.254: J14.52@27.535,46.355 27.94,46.355 30.471,43.824 J12.52@39.605,43.824 ; v1(73.509,41.148) 73.509,26.67 77.573,22.606 v1@77.573,20.574 ; v1(89.662,20.574) 89.916,20.32 v1(89.916,12.319) ; v1(115.927,12.065) 115.941,12.051 R61.2@116.943,12.051
  Bottom Layer w0.254: v1(37.822,43.815) 37.949,43.815 39.981,41.783 47.855,41.783 48.49,41.148 v1(73.509,41.148) ; v1(77.597,20.574) v1(89.662,20.574) ; v1(89.916,12.319) 90.17,12.065 v1(115.927,12.065)
CAN_N: J4.2 R13.2 U2.6 | length 11.5
  Top Layer w0.152: U2.6@119.541,68.326 120.372,68.326 120.842,68.796 123.726,68.796 R13.2@124.436,68.086 125.071,68.086 125.781,68.796 127.76,68.796 J4.2@129.5,67.056
CAN_P: J4.1 R13.1 U2.7 | length 11.5
  Top Layer w0.152: U2.7@119.541,69.596 120.372,69.596 120.842,69.126 123.726,69.126 R13.1@124.436,69.836 125.071,69.836 125.781,69.126 127.76,69.126 J4.1@129.5,70.866
GND: BT1.2 C1.1 C2.1 C3.1 C4.1 C7.2 C8.1 C9.2 C10.2 C11.2 C12.2 C13.2 C14.2 C15.2 C16.2 C17.2 C18.2 C19.2 C20.1 C21.1 C22.1 C23.1 C24.2 C25.2 C26.2 C27.2 C28.2 C29.2 C30.2 C31.1 C32.1 C33.1 D1.2 J1.19 J2.0 J2.5 J3.4 J3.6 J3.8 J3.10 J3.12 J3.14 J3.16 J3.18 J3.20 J5.5 J6.4 J7.6 J7.G1 J7.G2 J7.G3 J7.G4 J10.8 J10.13 J10.14 J11.2 J11.3 J12.5 J12.6 J12.23 J12.24 J12.61 J12.62 J12.80 J13.1 J13.2 J13.4 J13.23 J13.24 J13.61 J13.62 J13.63 J14.5 J14.6 J14.23 J14.24 J14.61 J14.62 J14.80 J15.1 J15.2 J15.4 J15.23 J15.24 J15.61 J15.62 J15.63 J16.1 J16.32 JP6.1 JP7.1 Q1.E R18.1 R20.1 R21.1 R26.1 R28.1 R29.1 R35.2 R36.2 R37.2 R38.2 R39.1 R41.2 R47.2 S1.1 S1.2 S2.1 S2.2 S3.1 S3.2 S4.1 S4.2 S5.1 S5.2 U1.15 U2.2 U3.4 U4.5 U5.1 U6.25 | length 45
  Top Layer w0.254: C29.2@65.508,104.888 65.621,104.775 C22.1@67.173,104.775 ; C23.1@72.86,104.775 C20.1@74.412,104.775 ; v1@74.906,88.646 C28.2@74.906,89.803 ; C21.1@80.593,104.761 C30.2@82.145,104.761 ; v1(95.25,110.998) 95.265,110.983 U1.15@95.265,109.905
  Top Layer w0.508: v1(37.846,62.484) 38.106,62.224 J12.6@39.605,62.224 v2(41.805,62.224) J12.5@44.005,62.224 ; J12.24@39.605,55.024 41.783,55.024 ; v2(41.783,54.356) 41.783,55.024 ; J12.23@44.005,55.024 41.783,55.024 ; v1(63.627,98.044) C31.1@64.76,98.044 ; v1(66.04,101.727) R41.2@67.173,101.727 ; C22.1@67.173,104.775 67.173,105.781 v1(67.183,105.791) ; C23.1@72.86,104.775 72.86,105.753 v1(72.898,105.791) ; C21.1@80.48,104.648 80.48,105.626 v1(80.518,105.664) ; v1(88.773,110.236) C1.1@89.93,110.236 ; J13.62@89.605,39.824 91.948,39.824 ; J13.24@89.605,55.024 91.821,55.024 ; v2@91.821,54.508 91.821,55.024 ; v2(91.948,38.989) 91.948,39.824 ; J13.63@94.005,39.024 J13.61@94.005,39.824 91.948,39.824 ; v1(95.885,54.991) 95.852,55.024 J13.23@94.005,55.024 91.821,55.024
  Top Layer w0.762: J7.6@9.465,56.65 16.262,56.65 C12.2@16.588,56.325
  other v1: 74.93,88.646
  other v2: 18.542,2.794 22.225,2.794 25.654,2.794 28.829,2.794 41.402,3.302 44.577,3.302 123.825,3.937 123.825,5.969 1.524,8.001 1.524,11.176 46.736,11.303 87.249,13.843 46.609,14.097 1.524,14.478 87.249,16.383 46.609,16.891 1.524,18.415 86.614,19.812 46.609,20.066 1.651,21.844 86.614,22.86 46.609,23.241 59.436,24.638 76.835,25.273 86.614,25.527 117.348,26.289 76.835,27.432 59.436,27.686 1.524,28.575 117.348,29.083 76.835,29.337 59.436,30.226 1.524,32.258 117.348,32.512 41.783,33.401 91.821,33.909 59.436,34.036 117.221,35.433 41.783,36.195 1.524,36.703 117.221,38.481 59.309,39.243 1.524,40.005 1.524,43.053 117.221,43.434 117.221,46.355 1.524,46.609 1.524,50.165 117.221,51.308 124.079,52.578 126.492,52.578 129.032,52.578 1.524,54.102 91.821,54.483 1.524,57.531 1.524,60.96 91.821,61.722 119.126,63.5 121.793,63.5 124.206,63.5 126.619,63.5 129.032,63.5 91.821,63.754 67.437,63.881 1.524,64.008 59.055,64.389 55.245,66.675 67.564,66.802 59.055,67.945 55.245,70.104 59.055,70.993 69.215,72.39 1.651,72.517 55.245,73.025 69.215,74.803 121.666,75.692 124.46,75.692 127.889,75.692 1.651,75.819 48.641,75.819 114.935,75.819 86.868,76.2 114.935,78.105 86.868,78.486 1.651,79.121 48.641,80.518 86.868,81.153 1.651,82.042 69.215,82.169 48.641,83.439 53.594,83.439 57.531,83.439 86.868,83.693 69.215,84.201 1.651,85.471 78.232,88.138 67.056,88.265 69.215,88.265 71.374,88.265 1.651,88.519 86.868,89.027 78.232,89.916 1.651,91.44 78.232,92.075 86.868,92.075 20.701,92.329 116.586,94.234 118.999,94.234 121.539,94.234 1.778,94.488 12.065,94.996 20.701,95.377 1.778,97.155 12.065,97.663 20.701,97.79 80.645,99.441 83.439,99.441 86.233,99.441 12.065,99.695 20.701,100.33 12.065,101.727 42.037,104.521 31.877,104.648 34.417,104.648 37.211,104.648 67.183,106.807 69.215,106.807 72.898,106.807 75.819,106.807 78.74,106.807 81.28,106.807 20.828,114.554 24.257,114.554 27.559,114.554 72.898,117.221 75.311,117.221 77.597,117.221 10.668,120.269 12.446,120.269 14.224,120.269 16.129,120.269 18.161,120.269 20.193,120.269 22.098,120.269 24.257,120.269 26.543,120.269 93.726,123.19 97.663,123.19 101.092,123.19 104.902,123.19 108.204,123.19 111.379,123.19 115.062,123.19 72.644,124.206 74.676,124.206 77.089,124.206
  other v3: 74.271,95.25 75.033,95.25 75.922,95.25 74.271,96.139 75.033,96.139 75.922,96.139 74.271,97.028 75.033,97.028 75.922,97.028
LINK_LED: J10.12 R35.1 U6.3 | length 36.6
  Top Layer w0.254: J10.12@68.281,123.01 68.281,122.129 63.095,116.943 63.095,100.203 64.238,99.06 67.159,99.06 68.683,97.536 71.096,97.536 72.243,96.389 U6.3@73.133,96.389
NetBT1_1: BT1.1 D7.2 | length 3.8
  Top Layer w0.508: BT1.1@12.065,21.3 12.736,21.971 D7.2@15.564,21.971
NetBUZ1_2: BUZ1.2 D3.1 Q1.C | length 14.9
  Top Layer w0.508: Q1.C@117.324,104.886 117.34,104.902 BUZ1.2@124.246,104.902 125.895,103.253 D3.1@125.895,97.663
NetC2_2: C2.2 U1.2 | length 2.2
  Top Layer w0.254: C2.2@95.236,101.346 95.265,101.375 U1.2@95.265,103.505
NetC5_1: C5.1 U1.3 | length 3.9
  Top Layer w0.254: C5.1@93.345,105.396 94.986,105.396 95.915,104.467 U1.3@95.915,103.505
NetC5_2: C5.2 U1.1 | length 1.3
  Top Layer w0.254: C5.2@93.345,103.646 93.486,103.505 U1.1@94.615,103.505
NetC6_1: C6.1 U1.4 | length 2.4
  Top Layer w0.254: U1.4@96.565,103.505 96.565,102.166 97.004,101.727 97.004,101.435 C6.1@96.915,101.346
NetC6_2: C6.2 U1.5 | length 2.9
  Top Layer w0.254: U1.5@97.215,103.505 97.215,102.532 98.401,101.346 C6.2@98.665,101.346
NetC8_2: C8.2 U1.6 | length 4.2
  Top Layer w0.254: U1.6@97.865,103.505 97.865,104.747 98.387,105.269 C8.2@100.56,105.269
NetC10_1: C10.1 J6.5 J6.6 R26.2 | length 18.5
  Top Layer w0.762: J6.6@123.246,91.533 123.894,91.533 125.311,92.95 R26.2@125.311,93.98 C10.1@126.99,93.98
  Bottom Layer w0.762: J6.5@123.246,78.393 J6.6@123.246,91.533
NetC11_1: C11.1 J5.6 J5.7 J5.8 J5.9 R29.2 | length 22.7
  Top Layer w0.508: J5.8@8.695,106.167 7.083,106.167 5.856,104.94 R29.2@5.856,104.14 C11.1@4.178,104.14 4.178,105.184 J5.9@3.195,106.167 J5.7@3.195,115.067 J5.6@8.695,115.067
NetC26_1: C26.1 C27.1 U6.6 | length 5.9
  Top Layer w0.254: C27.1@70.701,90.551 70.701,92.251 C26.1@70.905,92.456 70.905,93.535 72.259,94.889 U6.6@73.133,94.889
NetC31_2: C31.2 R40.2 U6.4 X1.1 | length 8.4
  Top Layer w0.254: C31.2@66.51,98.044 66.608,97.946 X1.1@66.608,96.354 ; X1.1@66.633,96.379 R40.2@68.937,96.379 70.856,96.379 71.346,95.889 U6.4@73.133,95.889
